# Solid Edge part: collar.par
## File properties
Title: Collar
Author: Abhinav Rai
Template: Normal.par
Last saved by: Robert a Rhodes jr
Revision: 6
Application: Solid Edge
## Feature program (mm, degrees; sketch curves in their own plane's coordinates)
sketch for "unnamed RevolvedProtrusion 1" plane through (0, 0, 0) normal (0, -1, 0) x-axis (1, 0, 0)
  line (6.5405, -15.9527) -> (9.1186, -15.9527)
  line (9.1186, -15.9527) -> (9.1186, -36.5775)
  line (9.1186, -36.5775) -> (6.5405, -36.5775)
  line (6.5405, -15.9527) -> (6.5405, -36.5775)
revolve "unnamed RevolvedProtrusion 1" add finite 360 deg
sketch for "unnamed Cutout 1" plane through (0, 0, 0) normal (0, -1, 0) x-axis (1, 0, 0)
  line (-1.1811, -15.9527) -> (1.1811, -15.9527)
  line (1.1811, -15.9527) -> (1.1811, -19.1277)
  line (1.1811, -19.1277) -> (-1.1811, -19.1277)
  line (-1.1811, -19.1277) -> (-1.1811, -15.9527)
extrude "unnamed Cutout 1" cut finite 50.8 symmetric
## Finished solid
Body 1: solid body, 11 faces, 26 edges, 16 vertices.
  Faces by surface: plane 9, cylinder 2
  Edges by curve: line 16, circle 10
Bounding box of the edges (mm): 18.237 x 18.237 x 20.625, from (-9.1186, -9.1186, -36.5775) to (9.1186, 9.1186, -15.9527).
Cylindrical faces by radius (mm): R6.5405 x1, R9.1186 x1
Planar faces by outward normal: +x 2, +z 4, -x 2, -z 1
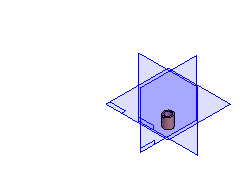
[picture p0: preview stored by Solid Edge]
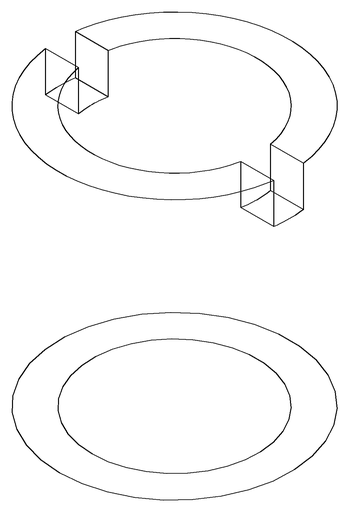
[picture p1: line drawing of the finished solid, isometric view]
